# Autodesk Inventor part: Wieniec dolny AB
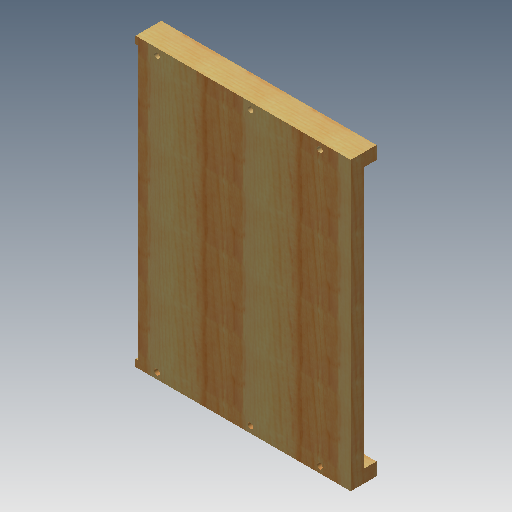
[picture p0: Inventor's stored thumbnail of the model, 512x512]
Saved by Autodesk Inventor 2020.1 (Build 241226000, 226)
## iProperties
Created: 2005-10
Part Number: Wieniec dolny AB
Document SubType Name: Modeling
Designer: F.Stasiak
Density: 1 g/cm^3
Material: Ogólny
Appearance: Drewno (sosna)
Manager: www.cadconsulting.pl
Company: Fabian Stasiak CAD Consulting
Author: F.Stasiak
Subject: Zbiór ćwiczeń. Autodesk Inventor 2020. Kurs podstawowy
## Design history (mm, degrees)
sketch "Szkic1"
  geometry: L1 (-150, 200)-(150, 200); L2 (150, 200)-(150, -200); L3 (150, -200)-(-150, -200); L4 (-150, -200)-(-150, 200); L5 (0, -200)-(0, 200); 2 further points
  constraints: 10 end point, 3 midpoint, 2 parallel, 1 coincident, 1 horizontal, 1 perpendicular, 1 other
  dimensions: "d0" = 300 distance of L2.end L3.end; "d1" = 400 distance of L3.end L1.start
extrude "Wyciągnięcie proste1" new body sketch "Szkic1" distance "d2" = 36; taper "d3" = 0 deg
feature "Skorupa1" dims "d4" = 18
sketch "Szkic2"
  geometry: L1 (-150, 182)-(150, 182) reference; L2 (150, 182)-(150, 200) reference; L3 (150, 200)-(-150, 200) reference; L4 (-150, 200)-(-150, 182) reference; L5 (150, -182)-(-150, -182) reference; L6 (-150, -182)-(-150, -200) reference; L7 (-150, -200)-(150, -200) reference; L8 (150, -200)-(150, -182) reference; L9 (-150, 191)-(150, 191); L10 (-150, -191)-(150, -191); L11 (-120, 191)-(-120, -191); L12 (-96, 191)-(-96, -191); L13 (76, 191)-(76, -191); L14 (100, 191)-(100, -191)
  constraints: 12 end point, 8 point on line, 4 midpoint, 2 perpendicular, 1 parallel, 1 vertical
  dimensions: "d5" = 24 distance of L12.start L11.start; "d6" = 24 distance of L14.start L13.start (= d5); "d7" = 30 distance from line of L11.start L4; "d8" = 50 distance from line of L2 L14.start
hole "Otwór1" sketch "Szkic2" at (-120, 191), (-96, 191), (100, 191), (76, 191), (-120, -191), (-96, -191), (76, -191), (100, -191) diameter "d9" = 8; stored, may be unused: countersink angle "d13" = 90 deg, drill point angle "d15" = 118 deg; dims "d10" = 6, "d11" = 4, "d12" = 2, "d14" = 20
sketch "Szkic3"
  geometry: L1 (150, 200)-(150, -200) reference; L2 (-150, 200)-(150, 200) reference; L3 (-150, -200)-(-150, 200) reference; L4 (150, -200)-(-150, -200) reference; L5 (-150, 191)-(150, 191); 3 further points
  constraints: 5 point on line, 2 end point, 1 perpendicular
  dimensions: "d27" = 9 distance between parallel lines of L2 L5; "d28" = 130 distance of point (10, 191) point (-120, 191); "d29" = 97 distance of point (107, 191) point (10, 191); "d30" = 30 distance from line of point (-120, 191) L3
hole "Otwór2" sketch "Szkic3" at (-120, 191), (10, 191), (107, 191) diameter "d31" = 8; stored, may be unused: countersink angle "d35" = 90 deg, drill point angle "d37" = 118 deg; dims "d32" = 6, "d33" = 4, "d34" = 2, "d36" = 15
mirror "Lustro1"
sketch "Szkic4"
  geometry: L1 (0, 0)-(0, 400) reference; L2 (0, 390)-(-8, 390); L3 (-8, 390)-(-8, 10); L4 (-8, 10)-(0, 10); L5 (0, 10)-(0, 390); L6 (-36, 0)-(0, 0) reference; L7 (-36, 400)-(0, 400) reference
  constraints: 8 end point, 2 parallel, 1 horizontal, 1 perpendicular, 1 point on line
  dimensions: "d62" = 8 distance between parallel lines of L5 L3; "d63" = 10 distance between parallel lines of L6 L4; "d64" = 10 distance between parallel lines of L7 L2
extrude "Wyciągnięcie proste2" cut sketch "Szkic4" distance "d65" = 3.5; taper "d66" = 0 deg
node "Bryła1"
node "Korpusy bryłowe"
node "Korpusy powierzchniowe"
node "Pętla rzutowana1"
node "Pętla rzutowana2"
node "Pętla rzutowana3"
